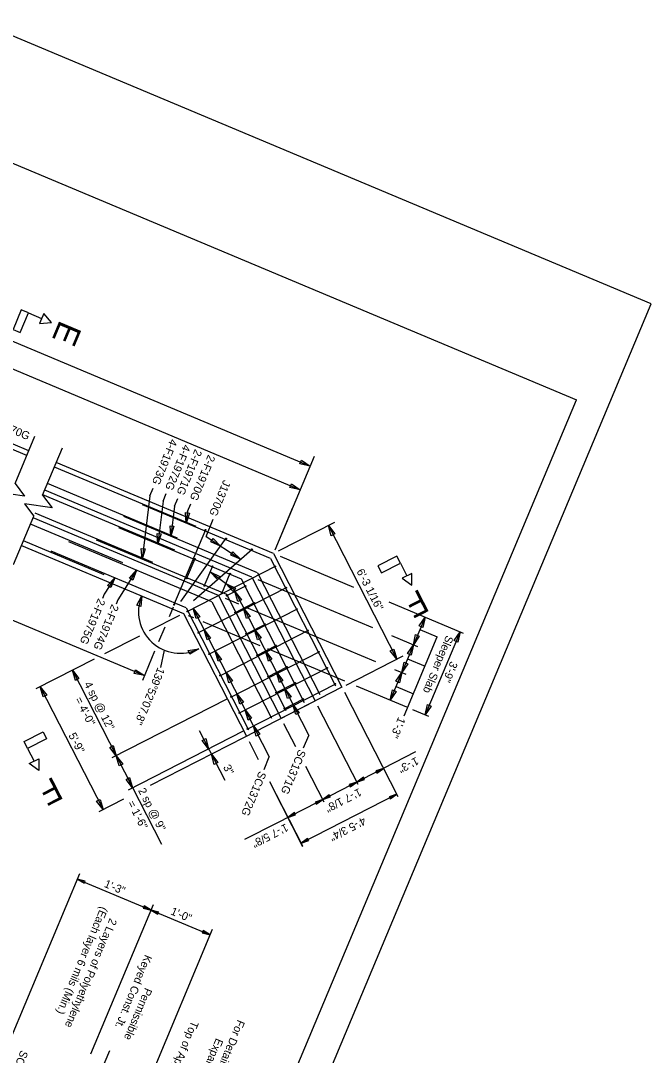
# Model space of a CAD drawing. Extents: x 1968564 to 1968711, y 796599 to 796794.
# Drawn here: x 1968661.3 to 1968700.7, y 796684.8 to 796749.4 of the extents above; entities that cross this region are included whole.
import ezdxf

# ---------------------------------------------------------------- set-up
doc = ezdxf.new("R2010")
doc.units = 0
for name, color, linetype in [('BR_AUTO DIMENSION', 7, 'Continuous'), ('BR_BORDER LINES', 7, 'Continuous'), ('BR_CONCRETE', 7, 'Continuous'), ('BR_REBAR', 7, 'Continuous'), ('BR_TABLE LINES', 7, 'Continuous'), ('BR_TEXT', 7, 'Continuous'), ('Level 31', 7, 'Continuous')]:
    doc.layers.add(name, color=color, linetype=linetype)

msp = doc.modelspace()

# ---------------------------------------------------------------- linework, layer by layer
at = {"layer": 'BR_AUTO DIMENSION'}
for p, q in [((1968627.909, 796743.166), (1968679.369, 796721.583)), ((1968644.739, 796734.365), (1968678.747, 796720.102)), ((1968624.948, 796726.966), (1968669, 796708.489)), ((1968660.909, 796720.49), (1968662.151, 796723.452)), ((1968662.633, 796719.767), (1968663.875, 796722.729)), ((1968677.171, 796716.343), (1968679.623, 796722.189)), ((1968669.338, 796719.724), (1968669.541, 796720.209)), ((1968669.338, 796719.724), (1968668.849, 796715.771)), ((1968670.163, 796719.378), (1968670.366, 796719.863)), ((1968670.876, 796719.079), (1968671.08, 796719.564)), ((1968670.163, 796719.378), (1968669.833, 796716.716)), ((1968670.876, 796719.079), (1968670.643, 796717.192)), ((1968671.701, 796718.733), (1968671.904, 796719.218)), ((1968677.171, 796716.343), (1968678.278, 796718.982)), ((1968660.812, 796715.426), (1968662.084, 796718.459)), ((1968671.701, 796718.733), (1968671.612, 796718.009)), ((1968672.851, 796717.19), (1968673.305, 796718.271)), ((1968677.392, 796716.275), (1968680.905, 796718.074)), ((1968680.498, 796717.866), (1968684.775, 796709.514)), ((1968672.851, 796717.19), (1968675.008, 796715.757)), ((1968677.476, 796715.944), (1968682.078, 796714.014)), ((1968668.507, 796715.068), (1968667.338, 796713.214)), ((1968673.118, 796714.974), (1968674.605, 796713.86)), ((1968667.144, 796714.605), (1968666.491, 796713.569)), ((1968676.093, 796714.491), (1968683.257, 796711.486)), ((1968674.605, 796713.86), (1968679.27, 796704.751)), ((1968666.491, 796713.569), (1968666.382, 796713.308)), ((1968667.338, 796713.214), (1968667.229, 796712.953)), ((1968674.041, 796713.318), (1968674.886, 796712.964)), ((1968684.271, 796713.094), (1968688.928, 796711.141)), ((1968670.796, 796712.772), (1968670.54, 796712.16)), ((1968671.985, 796712.655), (1968671.985, 796712.655)), ((1968672.049, 796712.687), (1968676.802, 796703.404)), ((1968675.389, 796712.753), (1968683.449, 796709.372)), ((1968671.197, 796712.251), (1968669.301, 796711.281)), ((1968671.731, 796712.254), (1968672.077, 796712.109)), ((1968672.649, 796711.869), (1968676.218, 796710.372)), ((1968686.544, 796712.141), (1968684.368, 796706.954)), ((1968670.27, 796711.517), (1968669.883, 796710.593)), ((1968686.217, 796711.363), (1968687.311, 796710.904)), ((1968688.731, 796711.224), (1968686.555, 796706.037)), ((1968668.681, 796710.963), (1968666.505, 796709.849)), ((1968684.447, 796710.987), (1968686.077, 796710.304)), ((1968685.248, 796705.984), (1968687.311, 796710.904)), ((1968669.637, 796710.008), (1968668.87, 796708.179)), ((1968670.236, 796710.078), (1968669.994, 796708.989)), ((1968676.684, 796710.177), (1968681.506, 796708.154)), ((1968665.865, 796709.521), (1968662.22, 796707.655)), ((1968681.604, 796707.89), (1968685.182, 796709.722)), ((1968685.456, 796709.547), (1968686.55, 796709.089)), ((1968664.501, 796708.823), (1968670.067, 796697.953)), ((1968684.639, 796708.873), (1968685.352, 796708.574)), ((1968682.232, 796707.85), (1968685.384, 796706.528)), ((1968684.73, 796707.818), (1968685.824, 796707.36)), ((1968662.489, 796707.793), (1968666.42, 796700.115)), ((1968684.856, 796700.915), (1968681.52, 796707.431)), ((1968674.152, 796707.024), (1968666.963, 796703.343)), ((1968682.358, 796701.679), (1968679.851, 796706.576)), ((1968685.757, 796706.371), (1968686.752, 796705.954)), ((1968678.464, 796704.04), (1968677.723, 796705.486)), ((1968675.171, 796705.017), (1968667.989, 796701.34)), ((1968675.231, 796704.627), (1968669.357, 796701.619)), ((1968672.431, 796705.053), (1968674.021, 796701.947)), ((1968678.946, 796703.979), (1968679.27, 796704.751)), ((1968675.54, 796704.369), (1968676.113, 796703.25)), ((1968676.479, 796702.632), (1968676.802, 796703.404)), ((1968685.942, 796703.718), (1968680.607, 796700.986)), ((1968680.23, 796700.59), (1968679.097, 796702.804)), ((1968676.823, 796701.864), (1968678.876, 796697.853)), ((1968678.909, 796697.79), (1968676.92, 796701.675)), ((1968667.683, 796700.762), (1968666.151, 796699.978)), ((1968680.607, 796700.986), (1968677.269, 796699.277)), ((1968684.773, 796701.078), (1968678.793, 796698.016)), ((1968677.269, 796699.277), (1968675.263, 796698.25)), ((1968664.941, 796696.102), (1968658.562, 796680.894)), ((1968664.804, 796695.777), (1968673.104, 796692.296)), ((1968669.552, 796694.168), (1968665.635, 796684.828)), ((1968673.24, 796692.621), (1968669.323, 796683.281)), ((1968661.621, 796672.639), (1968666.836, 796685.073))]:
    msp.add_line(p, q, dxfattribs=at)
for points in [[(1968678.818, 796721.95), (1968679.369, 796721.583), (1968678.721, 796721.719)], [(1968678.196, 796720.469), (1968678.747, 796720.102), (1968678.1, 796720.238)], [(1968671.816, 796718.639), (1968671.612, 796718.009), (1968671.567, 796718.67)], [(1968670.847, 796717.822), (1968670.643, 796717.192), (1968670.599, 796717.853)], [(1968680.676, 796717.228), (1968680.498, 796717.866), (1968680.9, 796717.34)], [(1968670.037, 796717.346), (1968669.833, 796716.716), (1968669.789, 796717.376)], [(1968673.291, 796717.048), (1968673.763, 796716.584), (1968673.153, 796716.84)], [(1968669.053, 796716.401), (1968668.849, 796715.771), (1968668.805, 796716.432)], [(1968674.536, 796716.221), (1968675.008, 796715.757), (1968674.398, 796716.012)], [(1968668.056, 796714.585), (1968668.507, 796715.068), (1968668.267, 796714.452)], [(1968673.564, 796714.484), (1968673.118, 796714.974), (1968673.714, 796714.684)], [(1968666.692, 796714.121), (1968667.144, 796714.605), (1968666.904, 796713.988)], [(1968674.539, 796713.754), (1968674.093, 796714.244), (1968674.688, 796713.954)], [(1968674.846, 796713.116), (1968674.661, 796713.751), (1968675.069, 796713.23)], [(1968668.532, 796712.88), (1968668.83, 796713.471), (1968668.772, 796712.811)], [(1968672.234, 796712.052), (1968672.049, 796712.687), (1968672.456, 796712.166)], [(1968675.384, 796712.064), (1968675.2, 796712.7), (1968675.607, 796712.178)], [(1968686.177, 796711.59), (1968686.544, 796712.141), (1968686.407, 796711.493)], [(1968672.917, 796710.717), (1968672.732, 796711.352), (1968673.14, 796710.831)], [(1968676.068, 796710.729), (1968675.883, 796711.365), (1968676.291, 796710.843)], [(1968686.185, 796710.963), (1968685.818, 796710.412), (1968685.954, 796711.06)], [(1968688.364, 796710.673), (1968688.731, 796711.224), (1968688.595, 796710.576)], [(1968685.452, 796709.861), (1968685.818, 796710.412), (1968685.682, 796709.764)], [(1968671.741, 796710.053), (1968672.392, 796710.17), (1968671.83, 796709.82)], [(1968673.601, 796709.382), (1968673.416, 796710.017), (1968673.823, 796709.496)], [(1968676.752, 796709.394), (1968676.567, 796710.029), (1968676.974, 796709.508)], [(1968684.59, 796710.15), (1968684.775, 796709.514), (1968684.367, 796710.036)], [(1968685.46, 796709.234), (1968685.093, 796708.683), (1968685.229, 796709.331)], [(1968664.683, 796708.186), (1968664.501, 796708.823), (1968664.906, 796708.299)], [(1968668.449, 796708.856), (1968669, 796708.489), (1968668.353, 796708.626)], [(1968674.284, 796708.046), (1968674.1, 796708.682), (1968674.507, 796708.16)], [(1968677.435, 796708.059), (1968677.25, 796708.694), (1968677.658, 796708.173)], [(1968684.726, 796708.132), (1968685.093, 796708.683), (1968684.957, 796708.035)], [(1968662.671, 796707.156), (1968662.489, 796707.793), (1968662.894, 796707.269)], [(1968674.968, 796706.711), (1968674.783, 796707.347), (1968675.191, 796706.825)], [(1968677.948, 796707.057), (1968677.763, 796707.693), (1968678.171, 796707.171)], [(1968684.735, 796707.505), (1968684.368, 796706.954), (1968684.504, 796707.602)], [(1968678.461, 796706.056), (1968678.276, 796706.692), (1968678.684, 796706.17)], [(1968686.922, 796706.588), (1968686.555, 796706.037), (1968686.691, 796706.684)], [(1968675.481, 796705.71), (1968675.296, 796706.346), (1968675.703, 796705.824)], [(1968675.994, 796704.709), (1968675.809, 796705.344), (1968676.216, 796704.823)], [(1968667.05, 796704.118), (1968667.236, 796703.482), (1968666.828, 796704.003)], [(1968672.829, 796704.549), (1968673.015, 796703.913), (1968672.606, 796704.434)], [(1968667.418, 796702.846), (1968667.236, 796703.482), (1968667.641, 796702.959)], [(1968673.367, 796702.943), (1968673.185, 796703.58), (1968673.59, 796703.056)], [(1968683.534, 796702.401), (1968683.945, 796702.695), (1968683.465, 796702.534)], [(1968668.076, 796702.115), (1968668.261, 796701.48), (1968667.853, 796702.001)], [(1968682.687, 796702.135), (1968682.276, 796701.841), (1968682.755, 796702.002)], [(1968681.865, 796701.546), (1968682.276, 796701.841), (1968681.796, 796701.68)], [(1968666.234, 796700.751), (1968666.42, 796700.115), (1968666.012, 796700.637)], [(1968679.737, 796700.456), (1968680.148, 796700.751), (1968679.669, 796700.59)], [(1968680.559, 796701.046), (1968680.148, 796700.751), (1968680.627, 796700.912)], [(1968684.362, 796700.783), (1968684.773, 796701.078), (1968684.294, 796700.917)], [(1968678.376, 796699.928), (1968677.965, 796699.633), (1968678.444, 796699.795)], [(1968679.204, 796698.311), (1968678.793, 796698.016), (1968679.273, 796698.177)], [(1968665.295, 796695.652), (1968664.804, 796695.777), (1968665.237, 796695.514)], [(1968668.925, 796693.967), (1968669.415, 796693.843), (1968668.983, 796694.105)], [(1968669.905, 796693.718), (1968669.415, 796693.843), (1968669.847, 796693.58)], [(1968672.614, 796692.42), (1968673.104, 796692.296), (1968672.672, 796692.558)]]:
    msp.add_lwpolyline(points, close=True, dxfattribs=at)
for points in [[(1968660.909, 796720.49), (1968661.511, 796719.702), (1968659.769, 796719.953), (1968660.361, 796719.182)], [(1968662.633, 796719.767), (1968663.234, 796718.979), (1968661.493, 796719.23), (1968662.084, 796718.459)]]:
    msp.add_lwpolyline(points, dxfattribs=at)
msp.add_arc((1968671.214, 796712.471), 2.585, 157.24601, 297.11484, dxfattribs=at)
at = {"layer": 'BR_BORDER LINES'}
for p in [(1968618.549, 796758.212), (1968643.927, 796601.539)]:
    msp.add_line(p, (1968696.012, 796725.723), dxfattribs=at)
at = {"layer": 'BR_CONCRETE'}
for p, q in [((1968661.766, 796722.533), (1968632.119, 796734.968)), ((1968677.074, 796716.113), (1968663.49, 796721.81)), ((1968675.717, 796714.649), (1968662.764, 796720.081)), ((1968673.623, 796713.494), (1968662.039, 796718.352)), ((1968661.314, 796716.623), (1968671.44, 796712.376)), ((1968677.074, 796716.113), (1968681.351, 796707.761)), ((1968675.717, 796714.649), (1968679.682, 796706.906)), ((1968673.623, 796713.494), (1968677.554, 796705.817)), ((1968671.44, 796712.376), (1968675.371, 796704.699)), ((1968681.351, 796707.761), (1968675.231, 796704.627)), ((1968677.413, 796705.745), (1968679.682, 796706.906))]:
    msp.add_line(p, q, dxfattribs=at)
at = {"layer": 'BR_REBAR'}
for p, q in [((1968661.645, 796722.245), (1968645.598, 796728.975)), ((1968672.237, 796717.803), (1968663.369, 796721.522)), ((1968671.077, 796717.069), (1968662.934, 796720.485)), ((1968670.896, 796716.332), (1968662.644, 796719.793)), ((1968676.884, 796715.798), (1968668.875, 796719.157)), ((1968669.53, 796715.549), (1968662.16, 796718.64)), ((1968676.072, 796714.915), (1968667.713, 796718.421)), ((1968667.643, 796715.527), (1968661.87, 796717.949)), ((1968667.379, 796717.745), (1968675.05, 796714.528)), ((1968670.848, 796712.895), (1968672.83, 796717.622)), ((1968666.484, 796714.794), (1968661.435, 796716.911)), ((1968673.221, 796713.091), (1968664.266, 796716.847)), ((1968674.147, 796713.549), (1968666.013, 796716.96)), ((1968671.272, 796713.123), (1968674.12, 796717.08)), ((1968671.609, 796712.732), (1968663.172, 796716.271)), ((1968672.074, 796713.184), (1968675.739, 796716.398)), ((1968671.632, 796714.538), (1968672.163, 796715.806)), ((1968676.884, 796715.798), (1968680.95, 796707.858)), ((1968671.663, 796712.49), (1968677.197, 796715.324)), ((1968672.741, 796714.073), (1968673.273, 796715.341)), ((1968676.072, 796714.915), (1968679.965, 796707.313)), ((1968673.83, 796713.616), (1968674.362, 796714.884)), ((1968675.05, 796714.528), (1968678.997, 796706.818)), ((1968672.346, 796711.155), (1968677.881, 796713.989)), ((1968674.116, 796713.472), (1968675.34, 796714.099)), ((1968673.221, 796713.091), (1968676.935, 796705.838)), ((1968677.865, 796706.287), (1968674.147, 796713.549)), ((1968674.654, 796712.42), (1968675.878, 796713.047)), ((1968671.609, 796712.732), (1968675.512, 796705.11)), ((1968673.03, 796709.82), (1968678.565, 796712.654)), ((1968675.338, 796711.085), (1968676.562, 796711.712)), ((1968673.714, 796708.484), (1968679.248, 796711.318)), ((1968674.397, 796707.149), (1968679.932, 796709.983)), ((1968676.022, 796709.75), (1968677.245, 796710.377)), ((1968674.91, 796706.148), (1968680.445, 796708.982)), ((1968676.705, 796708.415), (1968677.929, 796709.042)), ((1968675.423, 796705.147), (1968680.957, 796707.981)), ((1968677.218, 796707.414), (1968678.442, 796708.04)), ((1968677.731, 796706.412), (1968678.955, 796707.039))]:
    msp.add_line(p, q, dxfattribs=at)
for centre in [(1968672.818, 796717.593), (1968674.102, 796717.054), (1968675.716, 796716.377), (1968672.151, 796715.778), (1968673.26, 796715.312), (1968677.169, 796715.31), (1968671.644, 796714.567), (1968674.35, 796714.855), (1968672.753, 796714.102), (1968673.842, 796713.645), (1968675.312, 796714.085), (1968677.853, 796713.974), (1968674.144, 796713.486), (1968675.85, 796713.033), (1968670.86, 796712.924), (1968671.691, 796712.504), (1968674.682, 796712.435), (1968678.537, 796712.639), (1968676.534, 796711.698), (1968672.374, 796711.169), (1968675.366, 796711.1), (1968679.22, 796711.304), (1968677.218, 796710.363), (1968673.058, 796709.834), (1968676.049, 796709.764), (1968679.904, 796709.969), (1968673.742, 796708.499), (1968676.733, 796708.429), (1968677.901, 796709.027), (1968680.417, 796708.968), (1968678.414, 796708.026), (1968680.93, 796707.966), (1968674.425, 796707.164), (1968677.246, 796707.428), (1968678.927, 796707.025), (1968674.938, 796706.162), (1968677.759, 796706.427), (1968675.451, 796705.161)]:
    msp.add_circle(centre, 0.0313, dxfattribs=at)
at = {"layer": 'BR_TABLE LINES'}
for p, q in [((1968661.753, 796731.149), (1968662.573, 796730.805)), ((1968685.008, 796715.514), (1968685.413, 796714.723)), ((1968661.694, 796703.935), (1968662.099, 796703.144))]:
    msp.add_line(p, q, dxfattribs=at)
for points in [[(1968660.786, 796730.108), (1968661.237, 796729.919), (1968661.753, 796731.149), (1968661.302, 796731.338)], [(1968662.444, 796730.497), (1968663.187, 796730.547), (1968662.701, 796731.112)], [(1968683.599, 796715.342), (1968683.821, 796714.907), (1968685.008, 796715.514), (1968684.785, 796715.95)], [(1968685.117, 796714.571), (1968685.717, 796714.13), (1968685.71, 796714.875)], [(1968662.658, 796704.978), (1968662.881, 796704.543), (1968661.694, 796703.935), (1968661.471, 796704.371)], [(1968662.396, 796703.296), (1968662.403, 796702.551), (1968661.803, 796702.992)]]:
    msp.add_lwpolyline(points, close=True, dxfattribs=at)
at = {"layer": 'Level 31'}
msp.add_lwpolyline([(1968619.541, 796765.748), (1968563.846, 796632.955), (1968644.997, 796598.919), (1968700.693, 796731.712)], close=True, dxfattribs=at)

# ---------------------------------------------------------------- texts
at = {"layer": 'BR_AUTO DIMENSION'}
for s, rotation, p in [('6\'-3 1/16"', 297.11484, (1968682.242, 796715.008)), ('3\'-9"', 247.24601, (1968688.147, 796709.42)), ('139%%d52\'07.8"', 247.24601, (1968669.835, 796709.037)), ('4 sp @ 12"', 297.11484, (1968665.211, 796707.958)), ('= 4\'-0"', 297.11484, (1968664.636, 796706.995)), ('5\'-9"', 297.11484, (1968664.235, 796704.766)), ('1\'-3"', 207.11484, (1968685.992, 796703.426)), ('3"', 297.11484, (1968673.903, 796702.773)), ('2 sp @ 9"', 297.11484, (1968668.586, 796701.314)), ('1\'-7 1/8"', 207.11484, (1968682.42, 796701.474)), ('= 1\'-6"', 297.11484, (1968667.921, 796700.528)), ('4\'-5 3/4"', 207.11484, (1968682.692, 796699.677)), ('1\'-7 5/8"', 207.11484, (1968677.836, 796699.266)), ('1\'-3"', 337.24601, (1968666.438, 796695.3)), ('1\'-0"', 337.24601, (1968670.596, 796693.586))]:
    msp.add_text(s, height=0.5, rotation=rotation, dxfattribs=at).set_placement(p)
at = {"layer": 'BR_TEXT'}
for s, height, rotation, p in [('E', 1.5, 247.24601, (1968663.721, 796730.755)), ('2-A1970G', 0.4999, 337.24601, (1968658.898, 796724.371)), ('4-F1973G', 0.4999, 247.24601, (1968670.624, 796723.314)), ('4-F1972G', 0.4999, 247.24601, (1968671.449, 796722.968)), ('2-F1971G', 0.4999, 247.24601, (1968672.163, 796722.669)), ('2-F1970G', 0.4999, 247.24601, (1968672.988, 796722.323)), ('J1370G', 0.4999, 247.24601, (1968673.945, 796720.74)), ('F', 1.5, 207.11484, (1968686.228, 796713.929)), ('2-F1975G', 0.4999, 247.24601, (1968666.113, 796713.343)), ('2-F1974G', 0.4999, 247.24601, (1968666.96, 796712.987)), ('Sleeper Slab', 0.49995, 247.24601, (1968687.881, 796711.043)), ('1\'-3"', 0.4999, 247.24601, (1968684.881, 796705.938)), ('SC1371G', 0.4999, 247.24601, (1968678.651, 796703.914)), ('F', 1.5, 207.11484, (1968663.338, 796702.208)), ('SC1372G', 0.4999, 247.24601, (1968676.177, 796702.552)), ('(Each layer 6 mils (Min.)', 0.49995, 247.24601, (1968666.28, 796694.093)), ('2 Layers of Polyethylene', 0.49995, 247.24601, (1968666.843, 796693.368)), ('Keyed Const. Jt.', 0.49995, 247.24601, (1968669.042, 796691.088)), ('Permissible', 0.49995, 247.24601, (1968669.043, 796689.021)), ('Top of Approach Slab', 0.49995, 247.24601, (1968671.95, 796686.956)), ('For Details, see "Compression Seal ', 0.49995, 247.24601, (1968674.837, 796687.023)), ('Expansion Joint Details" sheet', 0.49995, 247.24601, (1968673.485, 796685.868)), ('SC1370G', 0.4999, 247.24601, (1968661.283, 796685.119))]:
    msp.add_text(s, height=height, rotation=rotation, dxfattribs=at).set_placement(p)

doc.saveas('drawing.dxf')
